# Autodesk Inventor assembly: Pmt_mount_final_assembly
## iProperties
Shininess: 64.0
Length Units: 11269
Angle Units: 11279
Time Units: 11290
Mass Units: 11283
Length Display Precision: 3
Angle Display Precision: 2
Compacted: True
Created: 2004-08
Part Number: Pmt_mount_final_assembly
Document SubType Name: Assembly
Designer: John Blackburn
Manufacturer: Standard
Standards Organization: Custom
Density: 0.0
Volumn: 0.0
Area: 0.0
PropertySet Name: Model Information
Control State: 0
Master: False
Checked Out: False
Author: John Blackburn
